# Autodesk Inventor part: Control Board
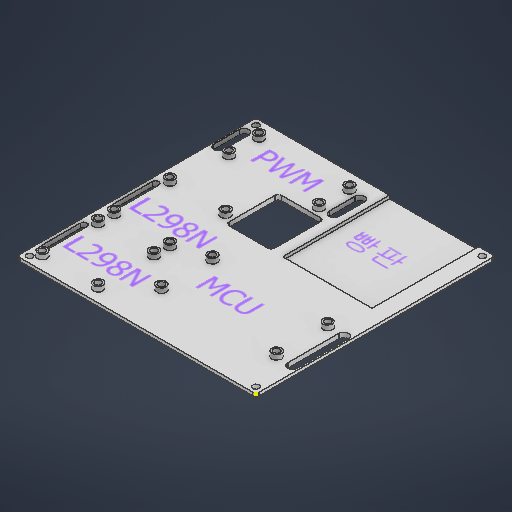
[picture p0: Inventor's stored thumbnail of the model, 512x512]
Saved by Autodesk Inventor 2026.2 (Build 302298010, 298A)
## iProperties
Created: 2026-04
Part Number: Control Board
Material: 일반
Document SubType Name: Modeling
Designer: work
Density: 1 g/cm^3
Appearance: 기본값
Author: work
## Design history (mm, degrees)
sketch "스케치1"
  geometry: L1 (150, -150)-(0, -150); L2 (0, -150)-(0, 0); L3 (0, 0)-(150, 0); L4 (150, 0)-(150, -150); L5 (150, -150)-(0, 0); L6 (0, -150)-(150, 0); L7 (4, -4)-(146, -4); L8 (146, -4)-(146, -146); L9 (146, -146)-(4, -146); L10 (4, -146)-(4, -4); L11 (4, -4)-(146, -146); L12 (146, -4)-(4, -146); L13 (14, -27)-(86.4, -27); L14 (10.2, -88)-(10.2, -78); L15 (7, -59)-(7, -27); L16 (4, -43)-(14, -43); L17 (4, -27)-(4, -59); L18 (14, -59)-(14, -27); L19 (50.2, -27)-(50.2, -59); L20 (10.2, -78)-(10.2, -8); L21 (90.2, -78)-(10.2, -78); L22 (86.4, -59)-(14, -59); L23 (86.4, -43)-(14, -43); L24 (90.2, -8)-(10.2, -78); L25 (10.2, -8)-(90.2, -8); L26 (10.2, -8)-(90.2, -78); L27 (86.4, -27)-(86.4, -59); L28 (90.2, -8)-(90.2, -78); L29 (1, -27)-(1, -59); L30 (107, -8)-(142, -8); L31 (107, -8)-(142, -43); L32 (142, -43)-(107, -43); L33 (142, -8)-(107, -43); L34 (142, -8)-(142, -43); L35 (107, -43)-(107, -8); L36 (107, -53)-(142, -53); L37 (107, -53)-(142, -88); L38 (142, -88)-(107, -88); L39 (142, -53)-(107, -88); L40 (142, -53)-(142, -88); L41 (107, -88)-(107, -53); L42 (109.7, -130.5)-(146, -130.5); L43 (138, -121)-(138, -140); L44 (138, -140)-(81.4, -140); L45 (81.4, -140)-(81.4, -121); L46 (138, -140)-(81.4, -121); L47 (81.4, -121)-(138, -121); L48 (81.4, -140)-(138, -121); L49 (146, -138.5)-(146, -122.5); L50 (143, -138.5)-(143, -122.5); L51 (109.7, -121)-(109.7, -140); L52 (109.7, -130.5)-(73.4, -130.5); L53 (76.4, -138.5)-(76.4, -122.5); L54 (73.4, -138.5)-(73.4, -122.5); L55 (70.4, -122.5)-(70.4, -138.5); L56 (149, -122.5)-(149, -138.5); L57 (66.2, -83)-(10.2, -83); L58 (10.2, -83)-(10.2, -166); L59 (10.2, -166)-(66.2, -166); L60 (66.2, -166)-(66.2, -83); L61 (102, -83)-(73.4, -83); L62 (73.4, -83)-(73.4, -116); L63 (73.4, -116)-(102, -116); L64 (102, -116)-(102, -83)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; C1 r 2 at (146, -4); C2 r 2 at (146, -146); C3 r 2 at (4, -4); C4 r 2 at (4, -146); C5 r 2 at (86.4, -59); C6 r 2 at (14, -59); C7 r 2 at (86.4, -27); C8 r 2 at (14, -27); C9 r 2 at (142, -8); C10 r 2 at (142, -43); C11 r 2 at (107, -8); C12 r 2 at (107, -43); C13 r 2 at (142, -53); C14 r 2 at (142, -88); C15 r 2 at (107, -53); C16 r 2 at (107, -88); C17 r 2 at (138, -140); C18 r 2 at (138, -121); C19 r 2 at (81.4, -121); C20 r 2 at (81.4, -140); A1 r 3 centre (4, -59) between (1, -59) and (7, -59); A2 r 3 centre (4, -27) between (7, -27) and (1, -27); A3 r 3 centre (146, -138.5) between (143, -138.5) and (149, -138.5); A4 r 3 centre (146, -122.5) between (149, -122.5) and (143, -122.5); A5 r 3 centre (73.4, -138.5) between (70.4, -138.5) and (76.4, -138.5); A6 r 3 centre (73.4, -122.5) between (76.4, -122.5) and (70.4, -122.5); A7 r 2 centre (146, -13) between (148, -13) and (144, -13); A8 r 2 centre (146, -38) between (144, -38) and (148, -38); A9 r 2 centre (146, -83) between (144, -83) and (148, -83); A10 r 2 centre (146, -58) between (148, -58) and (144, -58); 10 further points
  constraints: 148 end point, 30 centre point, 25 midpoint, 22 parallel, 21 coincident, 20 point on circle, 16 tangent, 11 perpendicular, 9 horizontal, 7 point on line, 7 symmetric about line, 5 collinear, 3 vertical, 2 other
  dimensions: "d0" = 150 distance of L2.end L3.end; "d1" = 150 distance of L1.end L2.end; "d2" = 4 distance between parallel lines of L4 L8; "d3" = 4 diameter of C1; "d4" = 4 diameter of C2; "d5" = 4 diameter of C3; "d6" = 4 diameter of C4; "d10" = 72.4 distance of L13.start L13.end; "d11" = 32 distance of L18.start L13.start; "d12" = 80 distance of L21.start L14.end; "d13" = 70 distance of L24.start L21.start; "d14" = 4 diameter of C8; "d15" = 4 diameter of C6; "d16" = 4 diameter of C7; "d17" = 4 diameter of C5; "d18" = 6 diameter of A1; "d19" = 10 distance from line of L13.start L17; "d20" = 32 distance of L17.start L17.end; "d21" = 4 vertical distance of L7.start L20.end; "d22" = 35 distance of L31.end L32.end; "d23" = 35 distance of L30.end L31.end; "d24" = 4 diameter of C9; "d25" = 4 diameter of C10; "d26" = 4 diameter of C11; "d27" = 4 diameter of C12; "d28" = 35 distance of L37.end L38.end; "d29" = 35 distance of L36.end L37.end; "d30" = 4 diameter of C13; "d31" = 4 diameter of C14; "d32" = 4 diameter of C15; "d33" = 4 diameter of C16; "d34" = 10 distance of C13.centre L31.end; "d37" = 56.6 distance of L45.end L43.start; "d38" = 19 distance of L44.end L45.end; "d39" = 4 diameter of C19; "d40" = 4 diameter of C20; "d41" = 4 diameter of C18; "d42" = 4 diameter of C17; "d43" = 16 distance of L54.start L54.end; "d44" = 8 distance between parallel lines of L45 L54; "d45" = 3 radius of A5; "d46" = 6 vertical distance of L8.end L43.end; "d47" = 56 distance of L59.end L58.end; "d48" = 83 distance of L58.end L57.end; "d49" = 5 distance between parallel lines of L21 L57; "d50" = 5 distance between parallel lines of L47 L63; "d51" = 5 distance between parallel lines of L41 L64; "d52" = 25 distance of L67.start L67.end; "d53" = 2 radius of A8; "d54" = 25 distance of L69.start L69.end; "d55" = 2 radius of A9
extrude "돌출1" new body sketch "스케치1" distance "d56" = 3; taper "d57" = 0 deg
extrude "돌출2" join sketch "스케치1" distance "d58" = 1; taper "d59" = 0 deg
sketch "스케치2"
  geometry: L1 (-150, 0)-(0, 0) reference; L2 (0, 0)-(0, 150) reference; L3 (0, 150)-(-10.2, 150) reference; L4 (-10.2, 150)-(-10.2, 83) reference; L5 (-10.2, 83)-(-66.2, 83) reference; L6 (-66.2, 83)-(-66.2, 150) reference; L7 (-66.2, 150)-(-150, 150) reference; L8 (-150, 150)-(-150, 0) reference; L9 (-148, 58)-(-148, 83) reference; L10 (-144, 83)-(-144, 58) reference; L11 (-148, 13)-(-148, 38) reference; L12 (-144, 38)-(-144, 13) reference; L13 (-102, 83)-(-102, 116) reference; L14 (-102, 116)-(-73.4, 116) reference; L15 (-73.4, 116)-(-73.4, 83) reference; L16 (-73.4, 83)-(-102, 83) reference; L17 (-70.4, 138.5)-(-70.4, 122.5) reference; L18 (-76.4, 122.5)-(-76.4, 138.5) reference; L19 (-149, 122.5)-(-149, 138.5) reference; L20 (-143, 138.5)-(-143, 122.5) reference; L21 (-1, 59)-(-1, 27) reference; L22 (-7, 27)-(-7, 59) reference; C1 r 2 at (-81.4, 140) reference; C2 r 2 at (-138, 121) reference; C3 r 2 at (-107, 88) reference; C4 r 2 at (-142, 88) reference; C5 r 2 at (-107, 43) reference; C6 r 2 at (-142, 43) reference; C7 r 2 at (-146, 146) reference; C8 r 2 at (-4, 4) reference; C9 r 2 at (-4, 146) reference; C10 r 2 at (-86.4, 59) reference; C11 r 2 at (-14, 59) reference; C12 r 2 at (-86.4, 27) reference; C13 r 2 at (-14, 27) reference; C14 r 2 at (-107, 8) reference; C15 r 2 at (-142, 53) reference; C16 r 2 at (-107, 53) reference; C17 r 2 at (-138, 140) reference; C18 r 2 at (-81.4, 121) reference; C19 r 2 at (-142, 8) reference; C20 r 2 at (-146, 4) reference; C21 r 3 at (-142, 8); C22 r 3 at (-142, 43); C23 r 3 at (-142, 53); C24 r 3 at (-142, 88); C25 r 2 at (-142, 8); C26 r 2 at (-142, 43); C27 r 2 at (-142, 53); C28 r 2 at (-142, 88); C29 r 2 at (-107, 88); C30 r 3 at (-107, 88); C31 r 2 at (-107, 53); C32 r 3 at (-107, 53); C33 r 2 at (-107, 43); C34 r 3 at (-107, 43); C35 r 2 at (-107, 8); C36 r 3 at (-107, 8); C37 r 2 at (-86.4, 27); C38 r 3 at (-86.4, 27); C39 r 2 at (-86.4, 59); C40 r 3 at (-86.4, 59); C41 r 2 at (-14, 27); C42 r 3 at (-14, 27); C43 r 2 at (-14, 59); C44 r 3 at (-14, 59); C45 r 2 at (-81.4, 121); C46 r 3 at (-81.4, 121); C47 r 2 at (-81.4, 140); C48 r 3 at (-81.4, 140); C49 r 2 at (-138, 121); C50 r 3 at (-138, 121); C51 r 2 at (-138, 140); C52 r 3 at (-138, 140); A1 r 2 centre (-146, 58) between (-148, 58) and (-144, 58) reference; A2 r 2 centre (-146, 83) between (-144, 83) and (-148, 83) reference; A3 r 2 centre (-146, 13) between (-148, 13) and (-144, 13) reference; A4 r 2 centre (-146, 38) between (-144, 38) and (-148, 38) reference; A5 r 3 centre (-73.4, 138.5) between (-70.4, 138.5) and (-76.4, 138.5) reference; A6 r 3 centre (-73.4, 122.5) between (-76.4, 122.5) and (-70.4, 122.5) reference; A7 r 3 centre (-146, 138.5) between (-143, 138.5) and (-149, 138.5) reference; A8 r 3 centre (-146, 122.5) between (-149, 122.5) and (-143, 122.5) reference; A9 r 3 centre (-4, 59) between (-1, 59) and (-7, 59) reference; A10 r 3 centre (-4, 27) between (-7, 27) and (-1, 27) reference; 1 further point
  constraints: 32 centre point, 20 coincident
  dimensions: "d60" = 6 diameter of C21; "d61" = 6 diameter of C22; "d62" = 6 diameter of C23; "d63" = 6 diameter of C24; "d64" = 4 diameter of C25; "d65" = 4 diameter of C26; "d66" = 4 diameter of C27; "d67" = 4 diameter of C28; "d68" = 6 diameter of C30; "d69" = 4 diameter of C29; "d70" = 6 diameter of C32; "d71" = 4 diameter of C31; "d72" = 6 diameter of C34; "d73" = 4 diameter of C33; "d74" = 6 diameter of C36; "d75" = 4 diameter of C35; "d76" = 6 diameter of C38; "d77" = 4 diameter of C37; "d78" = 6 diameter of C40; "d79" = 4 diameter of C39; "d80" = 6 diameter of C42; "d81" = 4 diameter of C41; "d82" = 6 diameter of C44; "d83" = 4 diameter of C43; "d84" = 6 diameter of C46; "d85" = 4 diameter of C45; "d86" = 6 diameter of C48; "d87" = 4 diameter of C47; "d88" = 6 diameter of C50; "d89" = 4 diameter of C49; "d90" = 6 diameter of C52; "d91" = 4 diameter of C51
extrude "돌출3" join sketch "스케치2" distance "d92" = 3; taper "d93" = 0 deg
fillet "모깎기1" dims "d94" = 2
chamfer "모따기1" distance "d95" = 1; stored, may be unused: second distance "d96" = 2, angle "d97" = 45 deg
sketch "스케치3" dims "d1" = 150
  geometry: L1 (-78.2, 51.337)-(-39.663, 51.337); L2 (-39.663, 51.337)-(-39.663, 37.272); L3 (-39.663, 37.272)-(-78.2, 37.272); L4 (-78.2, 37.272)-(-78.2, 51.337); L5 (-129.818, 123.067)-(-129.818, 137.132); L6 (-129.818, 137.132)-(-91.281, 137.132); L7 (-91.281, 137.132)-(-91.281, 123.067); L8 (-91.281, 123.067)-(-129.818, 123.067); L9 (-141.914, 59.213)-(-141.914, 73.278); L10 (-141.914, 73.278)-(-103.376, 73.278); L11 (-103.376, 73.278)-(-103.376, 59.213); L12 (-103.376, 59.213)-(-141.914, 59.213); L13 (-56.681, 108.158)-(-56.681, 122.223); L14 (-56.681, 122.223)-(-18.144, 122.223); L15 (-18.144, 122.223)-(-18.144, 108.158); L16 (-18.144, 108.158)-(-56.681, 108.158); L17 (-141.914, 17.581)-(-141.914, 31.646); L18 (-141.914, 31.646)-(-103.376, 31.646); L19 (-103.376, 31.646)-(-103.376, 17.581); L20 (-103.376, 17.581)-(-141.914, 17.581); 1 further point
  constraints: 10 other
node "솔리드1"
node "투영된 루프1"
